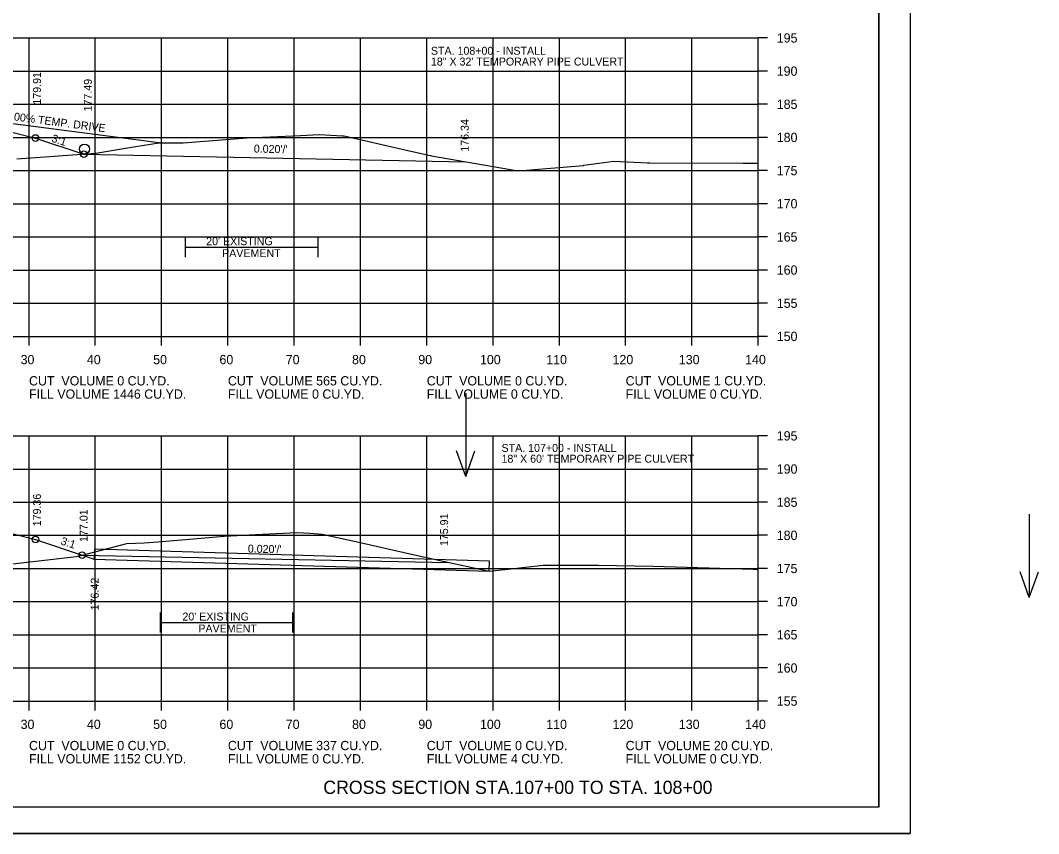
# Model space of a CAD drawing. Extents: x 915787 to 919910, y 133456 to 136717.
# Drawn here: x 916442.7 to 916596.3, y 133882.7 to 134005.3 of the extents above; entities that cross this region are included whole.
import ezdxf

# ---------------------------------------------------------------- set-up
doc = ezdxf.new("R2010")
doc.units = 0
for name, color, linetype in [('R_Axis', 7, 'Continuous'), ('R_Axis Annot', 7, 'Continuous'), ('R_Border', 7, 'Continuous'), ('R_Border Notes', 7, 'Continuous'), ('R_Draft', 7, 'Continuous'), ('R_Drive', 7, 'Continuous'), ('R_Exist Surface', 7, 'Continuous'), ('R_Exist Surface Annot', 7, 'Continuous'), ('R_Fin Surface', 7, 'Continuous'), ('R_Grid', 7, 'Continuous'), ('R_No Plot', 7, 'Continuous'), ('R_Water', 7, 'Continuous'), ('R_Water Annot', 7, 'Continuous'), ('R_Xsect Elev', 7, 'Continuous'), ('R_Xsect Slope', 7, 'Continuous')]:
    doc.layers.add(name, color=color, linetype=linetype)

msp = doc.modelspace()

# ---------------------------------------------------------------- linework, layer by layer
at = {"layer": 'R_Axis'}
for p, q in [((916553.98, 133957.69), (916553.98, 134002.69)), ((916555.38, 134002.69), (916553.98, 134002.69)), ((916555.38, 133997.69), (916553.98, 133997.69)), ((916555.38, 133992.69), (916553.98, 133992.69)), ((916555.38, 133987.69), (916553.98, 133987.69)), ((916555.38, 133982.69), (916553.98, 133982.69)), ((916555.38, 133977.69), (916553.98, 133977.69)), ((916555.38, 133972.69), (916553.98, 133972.69)), ((916555.38, 133967.69), (916553.98, 133967.69)), ((916555.38, 133962.69), (916553.98, 133962.69)), ((916273.98, 133957.69), (916553.98, 133957.69)), ((916443.98, 133956.29), (916443.98, 133957.69)), ((916453.98, 133956.29), (916453.98, 133957.69)), ((916463.98, 133956.29), (916463.98, 133957.69)), ((916473.98, 133956.29), (916473.98, 133957.69)), ((916483.98, 133956.29), (916483.98, 133957.69)), ((916493.98, 133956.29), (916493.98, 133957.69)), ((916503.98, 133956.29), (916503.98, 133957.69)), ((916513.98, 133956.29), (916513.98, 133957.69)), ((916523.98, 133956.29), (916523.98, 133957.69)), ((916533.98, 133956.29), (916533.98, 133957.69)), ((916543.98, 133956.29), (916543.98, 133957.69)), ((916553.98, 133956.29), (916553.98, 133957.69)), ((916555.38, 133957.69), (916553.98, 133957.69)), ((916553.98, 133902.69), (916553.98, 133942.69)), ((916555.38, 133942.69), (916553.98, 133942.69)), ((916555.38, 133937.69), (916553.98, 133937.69)), ((916555.38, 133932.69), (916553.98, 133932.69)), ((916555.38, 133927.69), (916553.98, 133927.69)), ((916555.38, 133922.69), (916553.98, 133922.69)), ((916555.38, 133917.69), (916553.98, 133917.69)), ((916555.38, 133912.69), (916553.98, 133912.69)), ((916555.38, 133907.69), (916553.98, 133907.69)), ((916273.98, 133902.69), (916553.98, 133902.69)), ((916443.98, 133901.29), (916443.98, 133902.69)), ((916453.98, 133901.29), (916453.98, 133902.69)), ((916463.98, 133901.29), (916463.98, 133902.69)), ((916473.98, 133901.29), (916473.98, 133902.69)), ((916483.98, 133901.29), (916483.98, 133902.69)), ((916493.98, 133901.29), (916493.98, 133902.69)), ((916503.98, 133901.29), (916503.98, 133902.69)), ((916513.98, 133901.29), (916513.98, 133902.69)), ((916523.98, 133901.29), (916523.98, 133902.69)), ((916533.98, 133901.29), (916533.98, 133902.69)), ((916543.98, 133901.29), (916543.98, 133902.69)), ((916553.98, 133901.29), (916553.98, 133902.69)), ((916555.38, 133902.69), (916553.98, 133902.69))]:
    msp.add_line(p, q, dxfattribs=at)
at = {"layer": 'R_Border'}
for q in [(916572.16, 134092.15), (916255.98, 133886.69)]:
    msp.add_line((916572.16, 133886.69), q, dxfattribs=at)
at = {"layer": 'R_Exist Surface'}
for points in [[(916442.16, 133984.46), (916454.05, 133985.31), (916458.55, 133986.06), (916463.54, 133986.88), (916465.67, 133986.87), (916467.15, 133986.86), (916467.21, 133986.87), (916474.31, 133987.42), (916476.88, 133987.64), (916476.88, 133987.65), (916484.93, 133988), (916487.73, 133988.13), (916487.73, 133988.13), (916491.26, 133987.95), (916491.54, 133987.94), (916501.57, 133985.63), (916504.55, 133984.94), (916504.71, 133984.92), (916517.77, 133982.63), (916527.61, 133983.48), (916527.64, 133983.49), (916527.66, 133983.49), (916532.21, 133984.12), (916537.3, 133983.85), (916537.63, 133983.85), (916551.69, 133983.83), (916553.34, 133983.81), (916553.98, 133983.81)], [(916440.23, 133923.25), (916451.11, 133924.51), (916452.6, 133924.83), (916458.76, 133926.45), (916461.36, 133926.56), (916463.4, 133926.7), (916469.37, 133927.21), (916473.42, 133927.56), (916478.17, 133927.81), (916484.36, 133928.14), (916486.4, 133928.01), (916488.2, 133927.87), (916493.28, 133926.77), (916501.69, 133924.85), (916506.01, 133923.87), (916513.38, 133922.27), (916516.21, 133922.6), (916521.56, 133923.18), (916529.86, 133923.17), (916532.58, 133923.15), (916538.11, 133923.03), (916553.21, 133922.59), (916553.98, 133922.59)]]:
    msp.add_lwpolyline(points, dxfattribs=at)
at = {"layer": 'R_Exist Surface Annot'}
for p, q in [((916467.54, 133972.64), (916467.54, 133969.64)), ((916487.54, 133972.64), (916487.54, 133969.64)), ((916467.54, 133971.14), (916487.54, 133971.14)), ((916463.76, 133916.04), (916463.76, 133913.04)), ((916483.75, 133916.04), (916483.75, 133913.04)), ((916463.76, 133914.54), (916483.75, 133914.54))]:
    msp.add_line(p, q, dxfattribs=at)
at = {"layer": 'R_Fin Surface'}
for points in [[(916367.16, 133979.17), (916382.97, 133984.44), (916389.01, 133985.95), (916396.97, 133987.94), (916402.97, 133988.5), (916413.97, 133989.52), (916424.97, 133990.54), (916430.97, 133991.1), (916439.17, 133989.05), (916444.97, 133987.6), (916452.24, 133985.18), (916509.8, 133984.03)], [(916371.08, 133919.92), (916382.97, 133923.89), (916389.01, 133925.4), (916396.97, 133927.39), (916402.97, 133927.95), (916413.97, 133928.97), (916424.97, 133929.99), (916430.97, 133930.55), (916439.17, 133928.5), (916444.97, 133927.05), (916452.02, 133924.7), (916507.27, 133923.6)]]:
    msp.add_lwpolyline(points, dxfattribs=at)
at = {"layer": 'R_Grid'}
for p, q in [((916273.98, 134002.69), (916553.98, 134002.69)), ((916443.98, 133957.69), (916443.98, 134002.69)), ((916453.98, 133957.69), (916453.98, 134002.69)), ((916463.98, 133957.69), (916463.98, 134002.69)), ((916473.98, 133957.69), (916473.98, 134002.69)), ((916483.98, 133957.69), (916483.98, 134002.69)), ((916493.98, 133957.69), (916493.98, 134002.69)), ((916503.98, 133957.69), (916503.98, 134002.69)), ((916513.98, 133957.69), (916513.98, 134002.69)), ((916523.98, 133957.69), (916523.98, 134002.69)), ((916533.98, 133957.69), (916533.98, 134002.69)), ((916543.98, 133957.69), (916543.98, 134002.69)), ((916553.98, 133957.69), (916553.98, 134002.69)), ((916273.98, 133997.69), (916553.98, 133997.69)), ((916273.98, 133992.69), (916553.98, 133992.69)), ((916273.98, 133987.69), (916553.98, 133987.69)), ((916273.98, 133982.69), (916553.98, 133982.69)), ((916273.98, 133977.69), (916553.98, 133977.69)), ((916273.98, 133972.69), (916553.98, 133972.69)), ((916273.98, 133967.69), (916553.98, 133967.69)), ((916273.98, 133962.69), (916553.98, 133962.69)), ((916273.98, 133957.69), (916553.98, 133957.69)), ((916273.98, 133942.69), (916553.98, 133942.69)), ((916443.98, 133902.69), (916443.98, 133942.69)), ((916453.98, 133902.69), (916453.98, 133942.69)), ((916463.98, 133902.69), (916463.98, 133942.69)), ((916473.98, 133902.69), (916473.98, 133942.69)), ((916483.98, 133902.69), (916483.98, 133942.69)), ((916493.98, 133902.69), (916493.98, 133942.69)), ((916503.98, 133902.69), (916503.98, 133942.69)), ((916513.98, 133902.69), (916513.98, 133942.69)), ((916523.98, 133902.69), (916523.98, 133942.69)), ((916533.98, 133902.69), (916533.98, 133942.69)), ((916543.98, 133902.69), (916543.98, 133942.69)), ((916553.98, 133902.69), (916553.98, 133942.69)), ((916273.98, 133937.69), (916553.98, 133937.69)), ((916273.98, 133932.69), (916553.98, 133932.69)), ((916273.98, 133927.69), (916553.98, 133927.69)), ((916273.98, 133922.69), (916553.98, 133922.69)), ((916273.98, 133917.69), (916553.98, 133917.69)), ((916273.98, 133912.69), (916553.98, 133912.69)), ((916273.98, 133907.69), (916553.98, 133907.69)), ((916273.98, 133902.69), (916553.98, 133902.69))]:
    msp.add_line(p, q, dxfattribs=at)
at = {"layer": 'R_No Plot'}
msp.add_line((916243.57, 133882.71), (916576.91, 133882.71), dxfattribs=at)
for points in [[(916243.57, 134096.05), (916576.91, 134096.05), (916576.91, 133882.71), (916243.57, 133882.71)], [(916489.9, 134092.15), (916489.9, 134082.27), (916525.63, 134082.27), (916525.63, 134079.35), (916548.83, 134079.35), (916548.83, 134056.14), (916572.16, 134056.14), (916572.16, 133886.69), (916255.98, 133886.69), (916255.98, 134092.15)]]:
    msp.add_lwpolyline(points, close=True, dxfattribs=at)
for centre in [(916444.97, 133987.6), (916444.97, 133987.6), (916452.24, 133985.18), (916452.24, 133985.18), (916444.97, 133927.05), (916444.97, 133927.05), (916452.02, 133924.7), (916452.02, 133924.7)]:
    msp.add_circle(centre, 0.5, dxfattribs=at)
at = {"layer": 'R_Water'}
for p, q in [((916452.24, 133985.18), (916509.8, 133984.03)), ((916452.02, 133924.7), (916507.27, 133923.6))]:
    msp.add_line(p, q, dxfattribs=at)
at = {"layer": 'R_Water Annot'}
for p, q in [((916509.85, 133949.13), (916509.85, 133936.56)), ((916509.85, 133936.56), (916508.45, 133940.41)), ((916509.85, 133936.56), (916511.25, 133940.41)), ((916594.88, 133930.88), (916594.88, 133918.32)), ((916594.88, 133918.32), (916593.48, 133922.16)), ((916594.88, 133918.32), (916596.28, 133922.16))]:
    msp.add_line(p, q, dxfattribs=at)
at = {"layer": 'R_Xsect Slope'}
for p, q in [((916463.54, 133986.88), (916430.97, 133991.1)), ((916452.06, 133924.69), (916453.8, 133924.11))]:
    msp.add_line(p, q, dxfattribs=at)
msp.add_lwpolyline([(916513.43, 133923.77), (916453.84, 133925.61), (916453.8, 133924.11), (916513.38, 133922.27), (916513.43, 133923.77)], dxfattribs=at)
msp.add_circle((916452.35, 133985.94), 0.75, dxfattribs=at)

# ---------------------------------------------------------------- texts
at = {"layer": 'R_Axis Annot'}
for s, p in [('195', (916556.78, 134001.99)), ('190', (916556.78, 133996.99)), ('185', (916556.78, 133991.99)), ('180', (916556.78, 133986.99)), ('175', (916556.78, 133981.99)), ('170', (916556.78, 133976.99)), ('165', (916556.78, 133971.99)), ('160', (916556.78, 133966.99)), ('155', (916556.78, 133961.99)), ('150', (916556.78, 133956.99)), ('30', (916442.71, 133953.49)), ('40', (916452.71, 133953.49)), ('50', (916462.71, 133953.49)), ('60', (916472.71, 133953.49)), ('70', (916482.71, 133953.49)), ('80', (916492.71, 133953.49)), ('90', (916502.71, 133953.49)), ('100', (916512.01, 133953.49)), ('110', (916522.01, 133953.49)), ('120', (916532.01, 133953.49)), ('130', (916542.01, 133953.49)), ('140', (916552.01, 133953.49)), ('195', (916556.78, 133941.99)), ('190', (916556.78, 133936.99)), ('185', (916556.78, 133931.99)), ('180', (916556.78, 133926.99)), ('175', (916556.78, 133921.99)), ('170', (916556.78, 133916.99)), ('165', (916556.78, 133911.99)), ('160', (916556.78, 133906.99)), ('155', (916556.78, 133901.99)), ('30', (916442.71, 133898.49)), ('40', (916452.71, 133898.49)), ('50', (916462.71, 133898.49)), ('60', (916472.71, 133898.49)), ('70', (916482.71, 133898.49)), ('80', (916492.71, 133898.49)), ('90', (916502.71, 133898.49)), ('100', (916512.01, 133898.49)), ('110', (916522.01, 133898.49)), ('120', (916532.01, 133898.49)), ('130', (916542.01, 133898.49)), ('140', (916552.01, 133898.49))]:
    msp.add_text(s, height=1.4, dxfattribs=at).set_placement(p)
at = {"layer": 'R_Border Notes'}
for s, p in [('CUT  VOLUME 0 CU.YD.', (916443.98, 133950.29)), ('CUT  VOLUME 565 CU.YD.', (916473.98, 133950.29)), ('CUT  VOLUME 0 CU.YD.', (916503.98, 133950.29)), ('CUT  VOLUME 1 CU.YD.', (916533.98, 133950.29)), ('FILL VOLUME 1446 CU.YD.', (916443.98, 133948.29)), ('FILL VOLUME 0 CU.YD.', (916473.98, 133948.29)), ('FILL VOLUME 0 CU.YD.', (916503.98, 133948.29)), ('FILL VOLUME 0 CU.YD.', (916533.98, 133948.29)), ('CUT  VOLUME 0 CU.YD.', (916443.98, 133895.29)), ('CUT  VOLUME 337 CU.YD.', (916473.98, 133895.29)), ('CUT  VOLUME 0 CU.YD.', (916503.98, 133895.29)), ('CUT  VOLUME 20 CU.YD.', (916533.98, 133895.29)), ('FILL VOLUME 1152 CU.YD.', (916443.98, 133893.29)), ('FILL VOLUME 0 CU.YD.', (916473.98, 133893.29)), ('FILL VOLUME 4 CU.YD.', (916503.98, 133893.29)), ('FILL VOLUME 0 CU.YD.', (916533.98, 133893.29))]:
    msp.add_text(s, height=1.4, dxfattribs=at).set_placement(p)
at = {"layer": 'R_Draft'}
msp.add_text('CROSS SECTION STA.107+00 TO STA. 108+00', height=2, dxfattribs=at).set_placement((916488.37, 133888.69))
at = {"layer": 'R_Drive'}
for s, p in [('STA. 108+00 - INSTALL', (916504.61, 134000.16)), ('18" X 32\' TEMPORARY PIPE CULVERT', (916504.61, 133998.53)), ('STA. 107+00 - INSTALL', (916515.26, 133940.27)), ('18" X 60\' TEMPORARY PIPE CULVERT', (916515.26, 133938.64))]:
    msp.add_text(s, height=1.2, dxfattribs=at).set_placement(p)
msp.add_text('13.00% TEMP. DRIVE', height=1.2, rotation=352.6075, dxfattribs=at).set_placement((916439.44, 133990.55))
at = {"layer": 'R_Exist Surface Annot'}
for s, p in [("20' EXISTING", (916470.71, 133971.44)), ('PAVEMENT', (916473.11, 133969.64)), ("20' EXISTING", (916467.12, 133914.84)), ('PAVEMENT', (916469.53, 133913.04))]:
    msp.add_text(s, height=1.2, dxfattribs=at).set_placement(p)
at = {"layer": 'R_Xsect Elev'}
for s, p in [('179.91', (916445.78, 133992.64)), ('177.49', (916453.45, 133991.61)), ('176.34', (916510.31, 133985.54)), ('179.36', (916445.77, 133929.05)), ('177.01', (916452.82, 133926.7)), ('175.91', (916507.2, 133926.07)), ('176.42', (916454.49, 133916.38))]:
    msp.add_text(s, height=1.2, rotation=90, dxfattribs=at).set_placement(p)
at = {"layer": 'R_Xsect Slope'}
for s, rotation, p in [('3:1', 341.5651, (916447.29, 133987.07)), ("0.020'/'", 358.8542, (916477.88, 133985.41)), ('3:1', 341.5651, (916448.66, 133926.35)), ("0.020'/'", 358.8542, (916476.98, 133925.09))]:
    msp.add_text(s, height=1.2, rotation=rotation, dxfattribs=at).set_placement(p)

doc.saveas('drawing.dxf')
